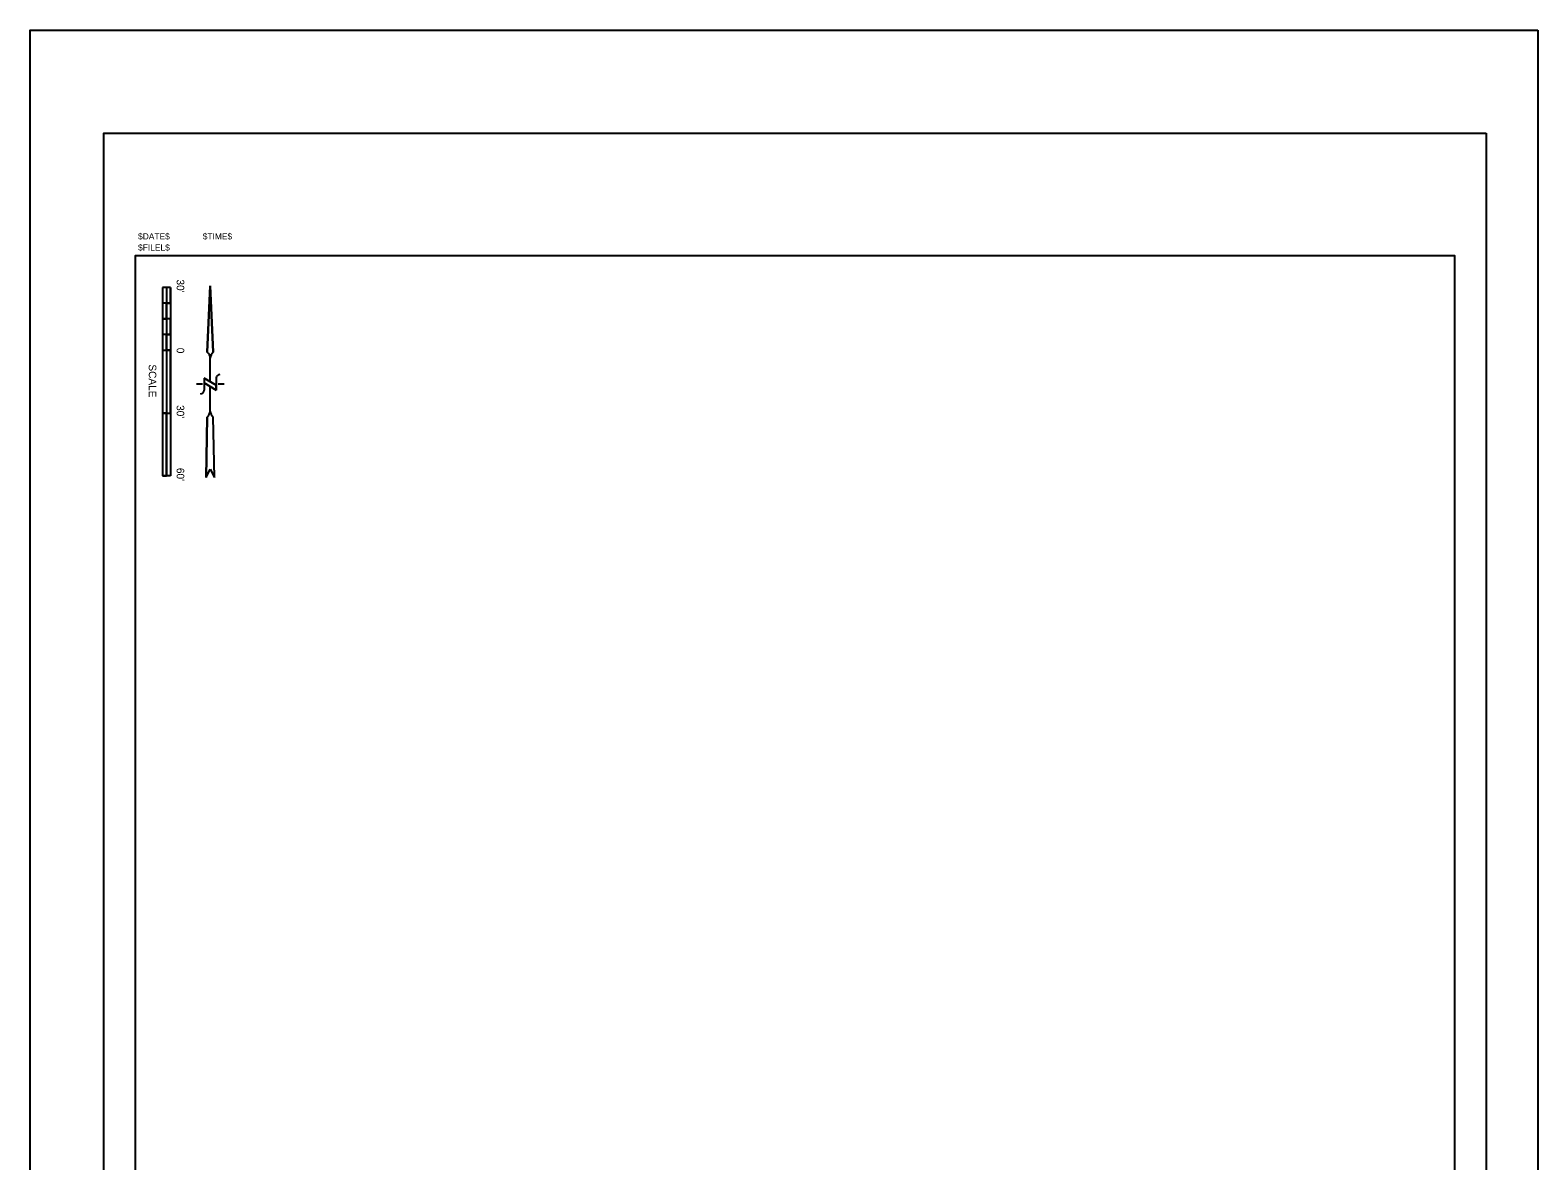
# Model space of a CAD drawing. Extents: x 2150486 to 2151206, y 144438 to 145518.
# Drawn here: x 2150486 to 2151206, y 144978 to 145518 of the extents above; entities that cross this region are included whole.
import ezdxf

# ---------------------------------------------------------------- set-up
doc = ezdxf.new("R2010")
doc.units = 0
for name, color, linetype in [('SHT_North_Arrow', 7, 'Continuous'), ('SHT_Plot_Shape_Half', 7, 'Continuous'), ('SHT_Scale', 7, 'Continuous'), ('SHT_Sheet_Border', 7, 'Continuous'), ('TOPO_Curb Back', 7, 'Continuous'), ('TOPO_Curb Gut', 7, 'Continuous')]:
    doc.layers.add(name, color=color, linetype=linetype)

msp = doc.modelspace()

# ---------------------------------------------------------------- linework, layer by layer
at = {"layer": 'SHT_North_Arrow'}
for p, q in [((2150570.91, 145363.85), (2150572.35, 145395.58)), ((2150572.35, 145395.58), (2150570.91, 145363.85)), ((2150572.35, 145395.58), (2150573.79, 145363.85)), ((2150573.79, 145363.85), (2150572.35, 145395.58)), ((2150572.35, 145349.81), (2150572.35, 145361.04)), ((2150568.61, 145348.66), (2150565.73, 145348.66)), ((2150575.23, 145348.09), (2150569.47, 145351.54)), ((2150569.47, 145351.54), (2150575.23, 145348.09)), ((2150569.47, 145351.54), (2150569.47, 145345.78)), ((2150572.35, 145349.81), (2150569.47, 145351.54)), ((2150569.47, 145351.54), (2150569.47, 145349.24)), ((2150575.23, 145345.78), (2150569.47, 145349.24)), ((2150575.23, 145348.09), (2150572.35, 145349.81)), ((2150572.35, 145335.71), (2150572.35, 145347.51)), ((2150575.23, 145351.54), (2150575.23, 145345.78)), ((2150575.23, 145345.78), (2150575.23, 145348.09)), ((2150578.97, 145348.66), (2150576.09, 145348.66)), ((2150570.34, 145304.05), (2150570.91, 145332.83)), ((2150570.91, 145332.83), (2150570.34, 145304.05)), ((2150574.37, 145304.05), (2150573.79, 145332.83)), ((2150574.37, 145304.05), (2150573.79, 145332.83)), ((2150570.34, 145304.05), (2150572.35, 145308.08)), ((2150570.34, 145304.05), (2150572.35, 145308.08)), ((2150572.35, 145308.08), (2150574.37, 145304.05)), ((2150572.35, 145308.08), (2150574.37, 145304.05))]:
    msp.add_line(p, q, dxfattribs=at)
for points in [[(2150569.47, 145349.24), (2150572.35, 145347.51), (2150575.23, 145345.78)], [(2150572.35, 145335.71), (2150572.35, 145335.71), (2150572.35, 145335.71)]]:
    msp.add_lwpolyline(points, dxfattribs=at)
for centre, radius, start, end in [((2150568.9, 145361.04), 3.45, 360, 54.38016), ((2150568.9, 145361.04), 3.45, 360, 54.38016), ((2150575.8, 145361.04), 3.45, 125.61984, 180), ((2150575.8, 145361.04), 3.45, 125.61984, 180), ((2150576.96, 145351.54), 1.73, 90, 180), ((2150567.74, 145345.78), 1.73, 270, 0), ((2150567.34, 145336.41), 5.06, 314.95671, 352.41889), ((2150567.34, 145336.41), 5.06, 314.95671, 352.059), ((2150577.36, 145336.41), 5.06, 187.58111, 225.04329), ((2150577.36, 145336.41), 5.06, 187.941, 225.04329)]:
    msp.add_arc(centre, radius, start, end, dxfattribs=at)
at = {"layer": 'SHT_Plot_Shape_Half'}
msp.add_lwpolyline([(2151181.58, 145468.57), (2151181.58, 144448.57), (2150521.58, 144448.57), (2150521.58, 145468.57)], close=True, dxfattribs=at)
at = {"layer": 'SHT_Scale'}
for p, q in [((2150553.31, 145394.81), (2150549.56, 145394.81)), ((2150549.56, 145394.81), (2150549.56, 145304.81)), ((2150551.43, 145394.81), (2150551.43, 145387.31)), ((2150553.31, 145394.81), (2150551.43, 145394.81)), ((2150551.43, 145394.81), (2150551.43, 145387.31)), ((2150553.31, 145394.81), (2150553.31, 145304.81)), ((2150553.31, 145387.31), (2150553.31, 145394.81)), ((2150553.31, 145387.31), (2150549.56, 145387.31)), ((2150551.43, 145387.31), (2150549.56, 145387.31)), ((2150549.56, 145387.31), (2150549.56, 145379.81)), ((2150551.43, 145387.31), (2150551.43, 145379.81)), ((2150551.43, 145387.31), (2150553.31, 145387.31)), ((2150551.43, 145379.81), (2150551.43, 145387.31)), ((2150553.31, 145379.81), (2150549.56, 145379.81)), ((2150553.31, 145379.81), (2150549.56, 145379.81)), ((2150549.56, 145379.81), (2150551.43, 145379.81)), ((2150551.43, 145379.81), (2150551.43, 145372.31)), ((2150553.31, 145379.81), (2150551.43, 145379.81)), ((2150551.43, 145379.81), (2150551.43, 145372.31)), ((2150553.31, 145372.31), (2150553.31, 145379.81)), ((2150553.31, 145372.31), (2150549.56, 145372.31)), ((2150551.43, 145372.31), (2150549.56, 145372.31)), ((2150549.56, 145372.31), (2150549.56, 145364.81)), ((2150551.43, 145372.31), (2150551.43, 145364.81)), ((2150551.43, 145372.31), (2150553.31, 145372.31)), ((2150551.43, 145364.81), (2150551.43, 145372.31)), ((2150549.56, 145364.81), (2150551.43, 145364.81)), ((2150549.56, 145364.81), (2150551.43, 145364.81)), ((2150551.43, 145364.81), (2150553.31, 145364.81)), ((2150551.43, 145364.81), (2150551.43, 145304.81)), ((2150553.31, 145364.81), (2150551.43, 145364.81)), ((2150551.43, 145364.81), (2150551.43, 145334.81)), ((2150553.31, 145334.81), (2150553.31, 145364.81)), ((2150549.56, 145334.81), (2150551.43, 145334.81)), ((2150551.43, 145334.81), (2150549.56, 145334.81)), ((2150549.56, 145334.81), (2150549.56, 145304.81)), ((2150551.43, 145334.81), (2150553.31, 145334.81)), ((2150551.43, 145334.81), (2150553.31, 145334.81)), ((2150551.43, 145304.81), (2150551.43, 145334.81)), ((2150551.43, 145304.81), (2150549.56, 145304.81)), ((2150549.56, 145304.81), (2150551.43, 145304.81)), ((2150553.31, 145304.81), (2150551.43, 145304.81))]:
    msp.add_line(p, q, dxfattribs=at)
at = {"layer": 'SHT_Sheet_Border'}
msp.add_lwpolyline([(2150536.58, 144465.07), (2150536.58, 145410.07), (2151166.58, 145410.07), (2151166.58, 144465.07)], close=True, dxfattribs=at)
at = {"layer": 'TOPO_Curb Gut'}
msp.add_lwpolyline([(2151206.32, 145517.69), (2151206.32, 144437.69), (2150486.32, 144437.69), (2150486.32, 145517.69)], close=True, dxfattribs=at)

# ---------------------------------------------------------------- texts
at = {"layer": 'SHT_Scale'}
for s, p in [("30'", (2150556.31, 145398.63)), ('0', (2150556.31, 145366)), ('SCALE', (2150542.96, 145358.07)), ("30'", (2150556.31, 145338.63)), ("60'", (2150556.31, 145308.63))]:
    msp.add_text(s, height=3.6, rotation=270, dxfattribs=at).set_placement(p)
at = {"layer": 'TOPO_Curb Back'}
for s, p in [('$DATE$', (2150537.85, 145417.71)), ('$TIME$', (2150568.74, 145417.71)), ('$FILEL$', (2150537.85, 145412.39))]:
    msp.add_text(s, height=3, rotation=360, dxfattribs=at).set_placement(p)

doc.saveas('drawing.dxf')
